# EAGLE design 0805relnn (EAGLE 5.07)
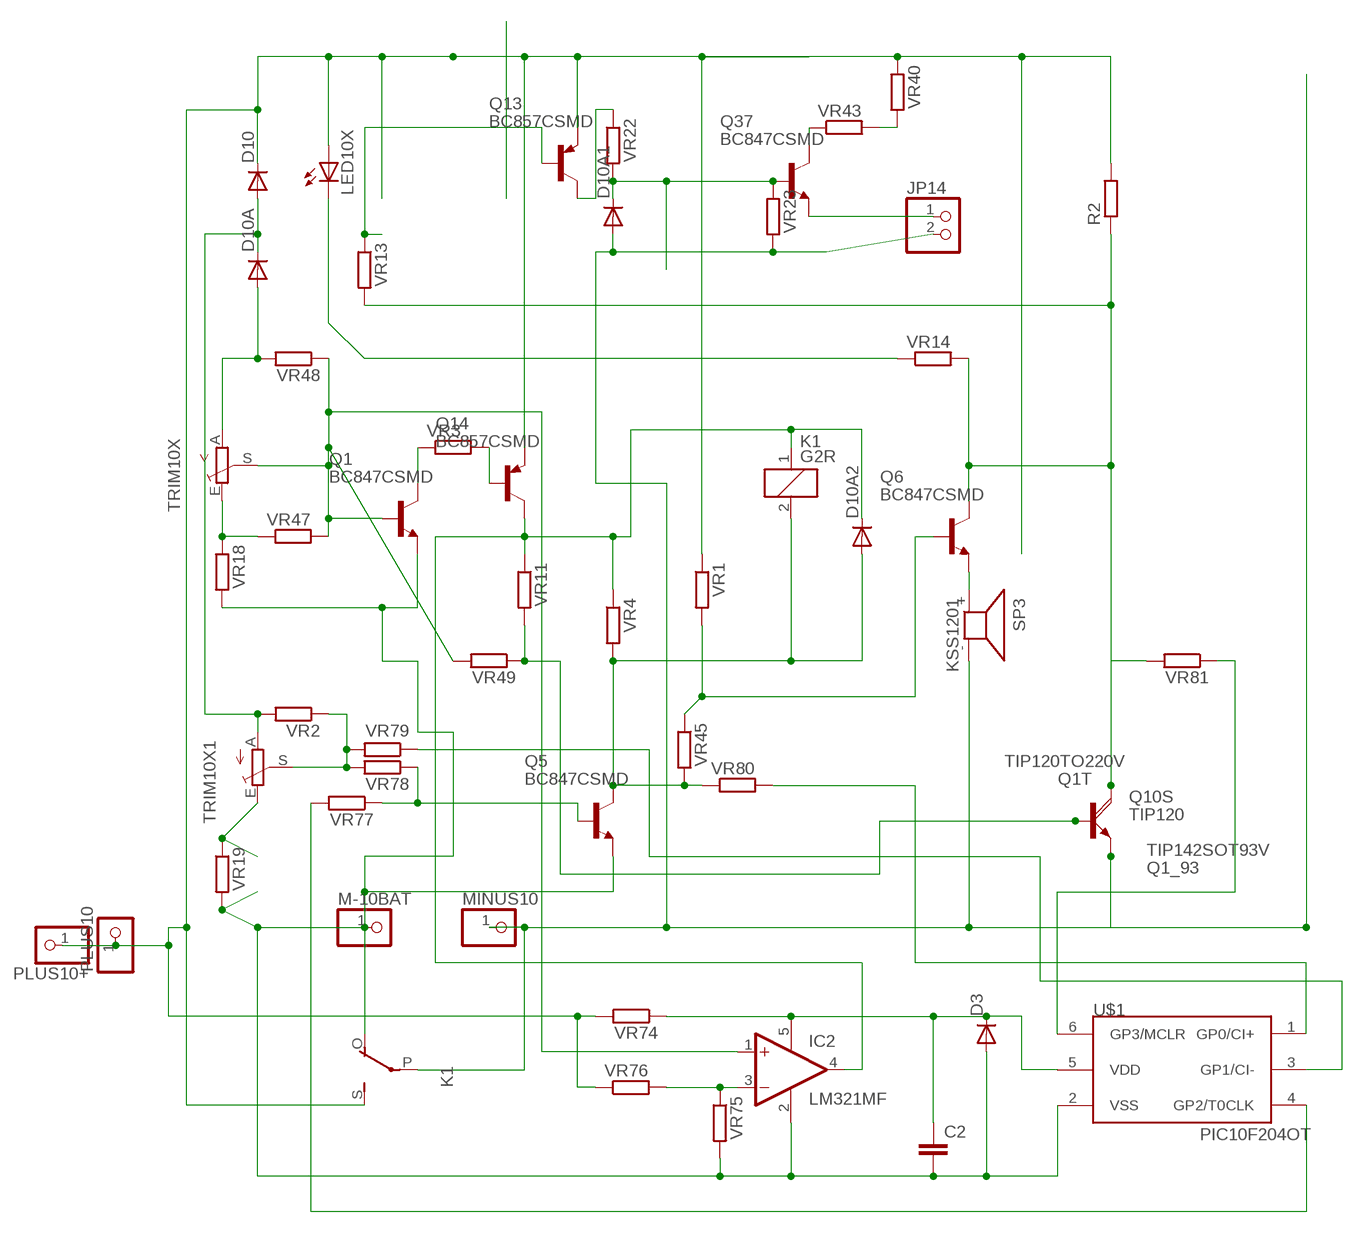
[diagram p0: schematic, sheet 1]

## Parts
C2  C-EUC0805  [C0805]
D3  DIODE-MINIMELF  [MINIMELF]
D10  DIODE-MINIMELF  [MINIMELF]
D10A  DIODE-MINIMELF  [MINIMELF]
D10A1  DIODE-MINIMELF  [MINIMELF]
D10A2  DIODE-MINIMELF  [MINIMELF]
IC2  LM321MF  [SOT23-5]
JP14  PINHD-1X2STR  [1X02]
K1  G2R  [G2R]
LED10X  LEDCHIPLED_1206  [CHIPLED_1206]
M-10BAT  PINHD-1X11X0.4  [1X01]
MINUS10  PINHD-1X14.5MM  [1X4MM5]
PLUS10  PINHD-1X14.5MM  [1X4MM5]
PLUS10+  PINHD-1X11X0.4  [1X01]
Q1  BC847CSMD  [SOT23]
Q1_93  TIP142SOT93V  [SOT93V]
Q1T  TIP120TO220V  [TO220AV]
Q5  BC847CSMD  [SOT23]
Q6  BC847CSMD  [SOT23]
Q10S  TIP120  TIP120DPAK  [D-PAK_TO252AA]
Q13  BC857CSMD  [SOT23-BEC]
Q14  BC857CSMD  [SOT23-BEC]
Q37  BC847CSMD  [SOT23]
R2  R-EU_CERAM85  [CERAM85]
SP3  KSS1201  [KSS1201]
TRIM10X  TRIM_EU-S64W  [S64W]
TRIM10X1  TRIM_EU-S64W  [S64W]
U$1  PIC10F204OT  [SOT23-6]
VR1  R-EU_R0805  [R0805]
VR2  R-EU_R0805  [R0805]
VR3  R-EU_R0805  [R0805]
VR4  R-EU_R0805  [R0805]
VR11  R-EU_R0805  [R0805]
VR13  R-EU_R0805  [R0805]
VR14  R-EU_R0805  [R0805]
VR18  R-EU_R1206  [R1206]
VR19  R-EU_R1206  [R1206]
VR22  R-EU_R0805  [R0805]
VR23  R-EU_R0805  [R0805]
VR40  R-EU_R1206  [R1206]
VR43  R-EU_R1206  [R1206]
VR45  R-EU_R0805  [R0805]
VR47  R-EU_R0805  [R0805]
VR48  R-EU_R0805  [R0805]
VR49  R-EU_R0805  [R0805]
VR74  R-EU_R0805  [R0805]
VR75  R-EU_R0603  [R0603]
VR76  R-EU_R0805  [R0805]
VR77  R-EU_R0805  [R0805]
VR78  R-EU_R0805  [R0805]
VR79  R-EU_R0805  [R0805]
VR80  R-EU_R0805  [R0805]
VR81  R-EU_R0805  [R0805]

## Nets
B: IC2.1(+IN) Q1.1(B) TRIM10X.S VR47.2 VR48.1 VR49.2
B2: U$1.4(GP2/T0CLK) VR77.2
E10: D10A1.A JP14.2 K1.P(2:P) MINUS10.1 Q1_93.E Q1T.E Q10S.3(E) SP3.- VR23.2
GP3: Q6.2(E) SP3.+
N$1: Q14.B VR3.2
N$2: Q1.3(C) VR3.1
N$11: LED10X.C VR14.1
N$14: D10A.A TRIM10X.A VR48.2
N$15: D10A2.C IC2.4(OUT) K1.1 Q14.C VR4.1 VR11.1
N$17: D10.A D10A.C TRIM10X1.A VR2.2
N$22: TRIM10X1.S VR2.1 VR78.2 VR79.2
N$23: Q13.B VR13.1
N$24: TRIM10X1.E VR19.1
N$25: Q1_93.B Q1T.B Q10S.1(B) VR11.2 VR49.1
N$128: TRIM10X.E VR18.1 VR47.1
N$136: JP14.1 Q37.2(E)
N$138: U$1.1(GP0/CI+) VR80.2
N$146: Q6.1(B) VR1.2 VR45.1
N$149: IC2.3(-IN) VR75.1 VR76.2
N$159: Q13.C VR22.1
N$163: VR40.2 VR43.2
N$164: Q37.3(C) VR43.1
N$165: U$1.3(GP1/CI-) VR79.1
N$168: Q5.1(B) VR77.1 VR78.1
N$169: D10A2.A K1.2 Q5.3(C) VR4.2 VR45.2 VR80.1
N$170: U$1.6(GP3/MCLR) VR81.1
N$179: D10A1.C Q37.1(B) VR22.2 VR23.1
PLUS11: D10.C K1.S(2:S) LED10X.A PLUS10+.1 PLUS10.1 Q13.E Q14.E R2.2 VR1.1 VR40.1 VR74.2 VR76.1
Q10C: Q1_93.C Q1T.C Q6.3(C) Q10S.4(C) R2.1 VR13.2 VR14.2 VR81.2
V3: C2.1 D3.C IC2.5(V+) U$1.5(VDD) VR74.1
VSS: C2.2 D3.A IC2.2(V-) K1.O(2:O) M-10BAT.1 Q1.2(E) Q5.2(E) U$1.2(VSS) VR18.2 VR19.2 VR75.2

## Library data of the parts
C2 = rcl:C-EU: CAPACITOR, European symbol
D3 D10 D10A D10A1 D10A2 = diode:DIODE-: DIODE
IC2 = linear:LM321?*: Low Power Single Op Amp Source: http://cache.national.com/ds/LM/LM321.pdf
JP14 = pinhead:PINHD-1X2: PIN HEADER
K1 = relay:G2R: RELAY 1 x switch, Omron
LED10X = led:LED: LED
M-10BAT MINUS10 PLUS10 PLUS10+ = pinhead:PINHD-1X1: PIN HEADER
Q1 Q5 Q6 Q37 = transistor-npn:BC847*: NPN Transistor
Q1_93 = transistor-power:TIP142: NPN DARLINGTON TRANSISTOR
Q1T Q10S = transistor-power:TIP120: NPN DARLINGTON TRANSISTOR
Q13 Q14 = transistor-pnp:BC857*: PNP Transistror
R2 = rcl:R-EU_: RESISTOR, European symbol
SP3 = buzzer:KSS1201: SPEAKER
TRIM10X TRIM10X1 = pot:TRIM_EU-: POTENTIOMETER
U$1 = microchip-3:PIC10F2*: uPC nW 0,25/0,5k Program Flash memory Comparator
VR1-VR4 VR11 VR13 VR14 VR18 VR19 VR22 VR23 VR40 VR43 VR45 VR47-VR49 VR74-VR81 = rcl-2:R-EU_: RESISTOR, European symbol

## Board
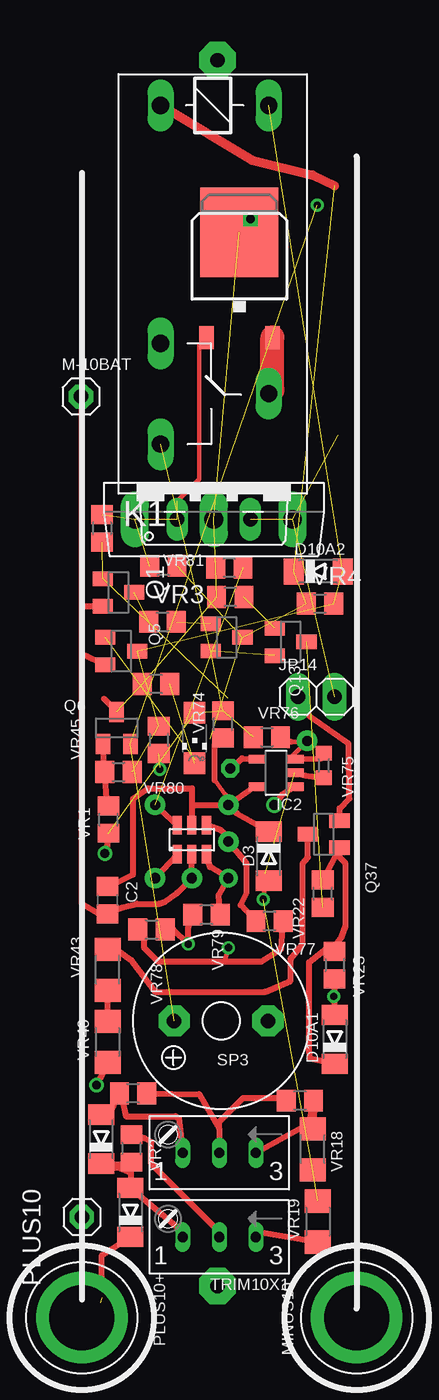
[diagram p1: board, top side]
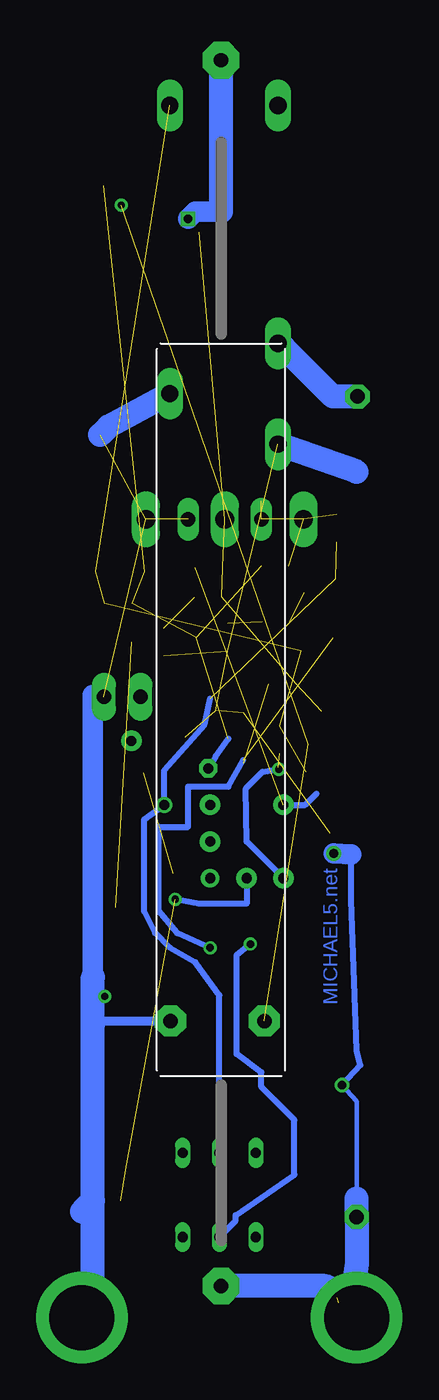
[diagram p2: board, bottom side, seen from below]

No outline drawn. Coordinates in mm, seen from the top.
Copper layers (1*16): Top 0.035mm / dielectric 1.5mm / Bottom 0.035mm
Design rules "default *": minimum track width 8mil, minimum drill 4mil, track to track 8mil, track to pad 8mil, pad to pad 8mil, via to via 8mil, smd to smd 8mil, copper to edge 40mil, drill to drill 8mil, minimum pad ring 1mil, minimum via ring 8mil, stop-mask expansion 4mil, vias tented up to drill 0mil, thermal gap 10mil

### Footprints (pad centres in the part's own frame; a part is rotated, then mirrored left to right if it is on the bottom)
C0805 = smd 1.3 x 1.5: 1 -0.95,0; 2 0.95,0
MINIMELF = smd 1.4 x 1.8: A 1.7,0; C -1.7,0
SOT23-5 = smd 0.6 x 1.2: 1 -0.95,-1.306; 2 0,-1.306; 3 0.95,-1.306; 4 0.95,1.306; 5 -0.95,1.306
1X02 = drill 1.016 pad 1.676 long: 1 -1.27,0; 2 1.27,0
G2R = drill 1.2 pad 1.778 long: 1 -2.54,-3.683; 2 -2.54,3.81; O 13.97,-3.683; P 17.45,3.81; S 20.955,-3.683
CHIPLED_1206 = smd 1.5 x 1.5: A 0,-1.75; C 0,1.75
1X01 = drill 1 pad 1.676 octagon: 1 0,0
1X4MM5 = drill 4.5 pad 6.35 round: 1 0,0
SOT23 = smd 1 x 1.4: 1 -0.95,-1.1; 2 0.95,-1.1; 3 0,1.1
SOT93V = drill 1.3 pad 1.676 long: B -5.461,-2.54; C 0,-2.54; E 5.461,-2.54
TO220AV = drill 1 pad 1.27 long: B -2.54,-2.54; C 0,-2.54; E 2.54,-2.54
D-PAK_TO252AA = smd 1 x 1.6: 1 -2.28,-4.8; 3 2.28,-4.8 | smd 5.4 x 6.2: 4 0,2.5
SOT23-BEC = smd 1 x 1.4: B -0.95,-1.1; C 0,1.1; E 0.95,-1.1
CERAM85 = drill 1 pad 2.54 octagon: 1 -42.5,0; 2 42.5,0
KSS1201 = drill 1 pad 2.159 octagon: + 3.251,0; - -3.251,0
S64W = drill 0.7 long: A 2.54,1.27; E -2.54,1.27; S 0,1.27
SOT23-6 = smd 0.635 x 1.27: 1 -1.016,-1.016; 2 0,-1.016; 3 1.016,-1.016; 4 1.016,1.016; 5 0,1.016; 6 -1.016,1.016
R0805 = smd 1.3 x 1.5: 1 -0.95,0; 2 0.95,0
R1206 = smd 1.6 x 1.803: 1 -1.422,0; 2 1.422,0
R0603 = smd 1 x 1.1: 1 -0.85,0; 2 0.85,0

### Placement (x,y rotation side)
C2  72.9,37.85 270 top
D3  84.07,40.89 270 top
D10  74.49,16.19 90 top
D10A  72.45,21.27 90 top
D10A1  88.65,28.19 90 top
D10A2  87.5,60.64 0 top
IC2  84.58,46.67 90 top
JP14  87.38,51.94 0 top
K1  80.26,90.42 270 top
LED10X  78.93,49.09 180 top
M-10BAT  71.06,72.77 0 top
MINUS10  90.17,8.89 0 top
PLUS10  71.12,8.89 0 top
PLUS10+  71.12,15.88 0 top
Q1  73.66,59.18 270 top
Q1_93  80.26,66.8 0 top
Q1T  80.26,66.8 0 top
Q5  73.85,55.12 270 top
Q6  73.53,49.78 0 top
Q10S  82.04,81.66 0 top
Q13  85.6,55.75 270 top
Q14  81.15,56.07 270 top
Q37  87.88,42.42 90 top
R2  80.52,53.59 270 bottom
SP3  80.77,29.46 180 top
TRIM10X  80.64,21.59 180 top
TRIM10X1  80.64,15.75 180 top
U$1  78.74,42.04 0 top
VR1  72.96,43.43 90 top
VR2  74.55,20.64 270 top
VR3  76.71,57.15 0 top
VR4  87.63,58.42 0 top
VR11  76.77,61.02 180 top
VR13  81.41,58.86 180 top
VR14  76.26,52.83 180 top
VR18  87.12,20.57 270 top
VR19  87.48,15.56 90 top
VR22  87.82,38.29 90 top
VR23  88.65,33.34 270 top
VR40  72.9,28 90 top
VR43  72.9,33.02 270 top
VR45  73.66,46.74 0 top
VR47  86.23,23.94 180 top
VR48  74.68,24.45 180 top
VR49  72.52,63.63 270 top
VR74  80.9,50.04 90 top
VR75  87.88,47.18 270 top
VR76  83.95,49.15 0 top
VR77  84.14,36.39 180 top
VR78  75.95,35.81 0 top
VR79  79.76,36.83 180 top
VR80  76.45,48.96 270 top
VR81  81.34,60.9 180 top

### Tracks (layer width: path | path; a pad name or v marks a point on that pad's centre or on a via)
B  (via drill 0.7)  (2 unrouted)
  Top 0.406: 80.64,21.97 80.64,22.48 82.3,24.13 85.19,24.13 VR47.2 | 80.64,21.97 TRIM10X.S | 80.64,21.97 79.25,24.38 VR48.1 | v84.45,44.45 85.09,45.24 IC2.1
  Bottom 0.406: TRIM10X.S 80.64,31.24 82.3,33.53 84.07,34.54 85.09,35.56 85.85,37.08 85.85,43.43 v84.45,44.45 84.45,46.86 81.66,50.04 81.28,51.82
B2  (via drill 0.7 pad 1.42)
  Top 0.406: VR77.2 82.13,37.5 82.55,38.35 82.55,40.39 v81.28,41.91 81.28,42.16 80.77,42.67 U$1.4
  Bottom 0.406: v81.28,41.91 81.28,42.16
E10  (via drill 0.5)  (3 unrouted)
  Top 0.406: MINUS10.1 88.9,10.92 | VR23.2 88.71,32.07 v88.58,31.18 D10A1.A
  Top 1.676: K1.P 84.32,73.22 Q10S.3
  Bottom 0.406: MINUS10.1 89.41,9.65 | v88.58,31.18 89.15,32.26 89.41,32.51 | 89.41,52.07 JP14.2
  Bottom 0.61: SP3.- 89.15,29.46 89.41,29.21
  Bottom 1.422: 89.41,32.51 89.41,52.07
  Bottom 1.676: 89.41,17.02 90.17,16.26 | 89.41,17.02 89.41,29.21 89.41,32.51 | K1.P 88.32,70.69 88.9,70.1 | 89.41,9.65 89.41,17.02
GP3  (via drill 0.5)  (2 unrouted)
  other vias: 87.44,86.04
N$1  (1 unrouted)
N$2  (1 unrouted)
N$11  (1 unrouted)
N$14
  Top 0.406: D10A.A 73.15,23.23 VR48.2 73.91,24.04 74.17,22.86 77.6,22.86 77.85,22.73 TRIM10X.A
N$15  (via drill 0.7 pad 1.27)  (5 unrouted)
  Top 0.406: IC2.4 82.23,47.69 v81.41,46.99
  Top 0.61: 88.65,87.38 87.12,88.14 82.93,89.15 K1.1
  Bottom 0.406: v81.41,46.99 80.9,47.82 80.01,49.02
N$17
  Top 0.406: VR2.2 73.94,19.53 D10A.C 72.64,19.25 73.66,19.3 74.5,18.97 D10.A 78.11,14.85 TRIM10X1.A
N$22  (via drill 0.5)
  Top 0.406: TRIM10X1.S 80.64,14.86 75.95,19.56 75.95,21.08 75.46,21.34 VR2.1 | VR79.2 78.49,35.9 v78.49,34.8 77.47,35.81 VR78.2
  Bottom 0.406: v78.49,34.8 79.44,34.04 79.44,27.18 77.72,25.91 77.72,24.89 75.44,22.61 75.44,18.8 79.5,16 79.5,15.62 TRIM10X1.S
N$23  (1 unrouted)
N$24
  Top 0.406: VR19.1 83.19,14.9 TRIM10X1.E
N$25  (4 unrouted)
  Top 0.305: Q10S.1 79.25,76.35 79.25,67.06 77.72,65.53
N$128
  Top 0.406: TRIM10X.E 86.89,22.35 VR47.1 87.25,23.77 VR18.1
N$136
  Top 0.406: Q37.2 88.98,44.22 89.66,44.9 89.62,48.68 86.61,50.8 86.61,51.56 JP14.1
N$138  (via drill 0.5, 0.7 pad 1.42)  (1 unrouted)
  Top 0.406: v76.2,39.37 U$1.1 | v76.52,46.93 76.54,47.03
  Bottom 0.406: v76.52,46.93 77.66,46.74 78.8,45.59 78.74,41.91 v76.2,39.37
N$146
  Top 0.406: VR1.2 72.96,44.77 72.83,44.9 VR45.1 Q6.1
N$149  (via drill 0.7 pad 1.42)
  Top 0.305: IC2.3 85.63,47.79 v86.74,48.9 86.56,48.82 85.63,48.82
  Top 0.406: IC2.3 87.73,47.69 VR75.1 | 85.63,48.82 VR76.2
N$159  (1 unrouted)
N$163
  Top 0.406: VR40.2 VR43.2
N$164
  Top 0.406: VR43.1 73.51,34.44 74.56,33.68 76.2,31.5 83.82,31.5 85.6,32.26 85.6,33.78 86.42,34.8 86.42,40.39 86.78,40.81 Q37.3
N$165  (via drill 0.7 pad 1.27)
  Top 0.406: U$1.3 80.01,40.13 v81.28,39.37 80.61,38.19 VR79.1
N$168  (via drill 0.5)  (1 unrouted)
  Top 0.305: 81.03,33.59 v81.28,34.54
  Top 0.406: VR77.1 84.94,34.46 83.57,33.59 81.03,33.59 76.39,33.59 75.44,34.54 75.44,35.73 VR78.1
  Bottom 0.406: v81.28,34.54 83.57,35.56 84.84,37.08 84.84,42.93 82.8,42.93 82.8,45.72 80.01,45.72 78.99,47.56
N$169  (5 unrouted)
N$170  (via drill 0.7 pad 1.42)  (1 unrouted)
  Top 0.406: U$1.6 v76.2,44.45
  Bottom 0.406: 73.91,45.21 74.68,44.45 v76.2,44.45
N$179
  Top 0.406: D10A1.C 86.95,26.85 86.87,27.43 86.87,33.53 88.14,34.54 88.58,34.54 | 88.58,34.54 VR23.1 | Q37.1 88.46,41.47 | 88.58,34.54 89.15,35.31 89.41,36.07 89.41,40.39 88.98,40.81 Q37.1 | Q37.1 VR22.2
PLUS11  (via drill 0.6)  (7 unrouted)
  Top 0.406: VR1.1 72.9,41.66 v72.71,41.08 | VR40.1 72.39,25.5 v72.14,25.02 | D10.C 72.5,13.22 72.5,10.27 PLUS10.1
  Bottom 0.305: 71.12,17.14 71.12,23.88 v72.14,25.02 | PLUS10+.1 71.12,11.18 72.39,9.91
  Bottom 0.406: 71.5,41.02 71.5,37.85 71.12,27.43 70.87,26.42 v72.14,25.02
  Bottom 1.422: 71.5,41.02 v72.71,41.08
  Bottom 1.676: 71.12,67.56 K1.S | 72.39,9.91 71.37,10.16 | 71.37,10.16 71.12,12.45 PLUS10+.1 71.12,17.14 | R2.2 73.32,11.09 71.37,10.16
Q10C  (via drill 0.6)  (5 unrouted)
  Top 0.406: Q6.3 73.53,50.93 72.64,51.82 | Q10S.4 82.8,84.92 v82.8,85.09
  Bottom 1.422: v82.8,85.09 82.3,85.6 80.52,85.6
  Bottom 1.676: 80.52,85.6 R2.1
V3  (via drill 0.7 pad 1.42)
  Top 0.305: 80.33,46.16 81.03,45.21 81.28,44.96 v81.28,44.45
  Top 0.406: 78.74,44.45 U$1.5 | 78.74,44.45 v81.28,44.45 | D3.C 81.87,43.86 v81.28,44.45 | C2.1 73.15,38.86 74.68,39.62 74.68,44.9 75.69,45.59 78.74,45.59 78.74,44.45 | IC2.5 83.02,45.68 v81.28,44.45 | 80.33,46.16 80.33,48.62 VR74.1
VSS  (via drill 0.5, 0.7 pad 1.42)  (3 unrouted)
  Top 0.305: v83.69,37.91 83.82,38.94 D3.A
  Top 0.406: U$1.2 v78.74,39.37 77.72,38.35 76.83,37.72 76.45,37.59 74.93,37.59 73.91,37.34 72.39,36.83 | M-10BAT.1 71.06,72.45 71.12,71.88 71.12,58.23 | C2.2 72.39,36.83 | 72.39,36.83 71.12,37.59 71.12,54.93 | IC2.2 86.61,46.48 VR75.2 | D3.A 83.82,39.7 | 71.12,54.93 Q5.2 | 71.12,58.23 Q1.2 | 71.12,54.93 71.12,58.23
  Bottom 0.406: v78.74,39.37 78.74,37.59 82.04,37.59 v83.69,37.91
  Bottom 1.676: M-10BAT.1 72.77,72.77 76.2,76.2 76.33,76.2 K1.O

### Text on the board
Bottom: MICHAEL5.net
tStop: MICHAEL5.net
